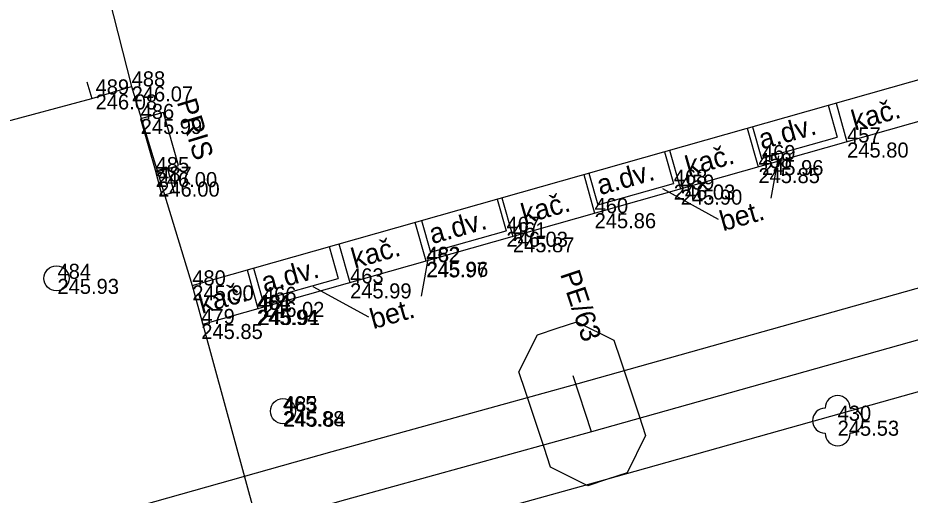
# Model space of a CAD drawing. Extents: x -599432 to -598680, y -1159407 to -1158632.
# Drawn here: x -599205.78 to -599187.97, y -1158928.37 to -1158918.84 of the extents above; entities that cross this region are included whole.
import ezdxf

# ---------------------------------------------------------------- set-up
doc = ezdxf.new("R2010")
doc.units = 0
for name, color, linetype in [('0004 VY - Body podrobné', 7, 'Continuous'), ('0005 VY - Body podrobné - čísla', 7, 'Continuous'), ('0006 VY - Body podrobné - výšky', 7, 'Continuous'), ('0007 ZA - Budova - zděná', 7, 'Continuous'), ('0007 ZAb - Budova - zděná podchodná', 7, 'Continuous'), ('0030 ZA - Chodník', 7, 'Continuous'), ('0031 ZA - Ostatní rozhraní', 7, 'Continuous'), ('0032 TE - Popis povrchu', 7, 'Continuous'), ('0035 ZA - Strom - značka', 7, 'Continuous'), ('0075 ZA - BVK - kanalizace - buňky', 7, 'Continuous'), ('0116 PV - budova převzatá z mapy', 7, 'Continuous'), ('0301 PV - RWE - popis', 7, 'Continuous'), ('0302 PV - RWE - NTL', 7, 'Continuous'), ('0303 PV - RWE - NTL přípojka', 7, 'Continuous'), ('0308 PV - RWE - ochranné pásmo', 7, 'Continuous'), ('0750 ZA - nerozlišené sítě - buňky', 7, 'Continuous'), ('0751 TE - nerozlišené sítě - popis', 7, 'Continuous')]:
    doc.layers.add(name, color=color, linetype=linetype)

msp = doc.modelspace()

# ---------------------------------------------------------------- linework, layer by layer
at = {"layer": '0004 VY - Body podrobné'}
for p, q in [((-599203.51, -1158920.21), (-599203.51, -1158920.21)), ((-599204.23, -1158920.37), (-599204.23, -1158920.37)), ((-599203.33, -1158920.86), (-599203.33, -1158920.86)), ((-599189.23, -1158921.33), (-599189.23, -1158921.33)), ((-599190.93, -1158921.68), (-599190.93, -1158921.68)), ((-599191, -1158921.84), (-599191, -1158921.84)), ((-599203.03, -1158921.92), (-599203.03, -1158921.92)), ((-599202.98, -1158922.11), (-599202.98, -1158922.11)), ((-599192.69, -1158922.17), (-599192.69, -1158922.17)), ((-599192.55, -1158922.27), (-599192.55, -1158922.27)), ((-599194.27, -1158922.74), (-599194.27, -1158922.74)), ((-599196.03, -1158923.11), (-599196.03, -1158923.11)), ((-599195.9, -1158923.22), (-599195.9, -1158923.22)), ((-599197.63, -1158923.72), (-599197.63, -1158923.72)), ((-599197.62, -1158923.71), (-599197.62, -1158923.71)), ((-599204.99, -1158924.05), (-599204.99, -1158924.05)), ((-599202.3, -1158924.18), (-599202.3, -1158924.18)), ((-599199.15, -1158924.14), (-599199.15, -1158924.14)), ((-599200.89, -1158924.51), (-599200.89, -1158924.51)), ((-599201.01, -1158924.67), (-599201.01, -1158924.67)), ((-599200.98, -1158924.67), (-599200.98, -1158924.67)), ((-599202.12, -1158924.95), (-599202.12, -1158924.95)), ((-599200.49, -1158926.69), (-599200.49, -1158926.69)), ((-599200.47, -1158926.7), (-599200.47, -1158926.7)), ((-599189.42, -1158926.88), (-599189.42, -1158926.88))]:
    msp.add_line(p, q, dxfattribs=at)
at = {"layer": '0007 ZA - Budova - zděná'}
for p, q in [((-599202.3, -1158924.18), (-599142.02, -1158907.12)), ((-599204.403, -1158920.118), (-599204.302, -1158920.451)), ((-599204.302, -1158920.451), (-599203.51, -1158920.21)), ((-599203.51, -1158920.21), (-599202.3, -1158924.18))]:
    msp.add_line(p, q, dxfattribs=at)
at = {"layer": '0007 ZAb - Budova - zděná podchodná'}
msp.add_line((-599207.036, -1158921.184), (-599204.302, -1158920.451), dxfattribs=at)
at = {"layer": '0030 ZA - Chodník'}
msp.add_line((-599202.3, -1158924.18), (-599199.63, -1158933.93), dxfattribs=at)
at = {"layer": '0031 ZA - Ostatní rozhraní'}
for p, q in [((-599202.089, -1158924.952), (-599182.511, -1158919.411)), ((-599189.607, -1158920.588), (-599189.428, -1158921.223)), ((-599189.452, -1158920.544), (-599189.235, -1158921.314)), ((-599191.225, -1158921.046), (-599191.007, -1158921.815)), ((-599191.118, -1158921.015), (-599190.938, -1158921.65)), ((-599190.938, -1158921.65), (-599189.428, -1158921.223)), ((-599192.876, -1158921.513), (-599192.696, -1158922.148)), ((-599192.773, -1158921.484), (-599192.555, -1158922.253)), ((-599194.488, -1158921.969), (-599194.27, -1158922.739)), ((-599194.387, -1158921.94), (-599194.207, -1158922.575)), ((-599194.207, -1158922.575), (-599192.696, -1158922.148)), ((-599196.215, -1158922.458), (-599196.035, -1158923.093)), ((-599196.123, -1158922.432), (-599195.905, -1158923.202)), ((-599197.856, -1158922.922), (-599197.638, -1158923.692)), ((-599197.725, -1158922.885), (-599197.546, -1158923.52)), ((-599197.546, -1158923.52), (-599196.035, -1158923.093)), ((-599199.57, -1158923.407), (-599199.391, -1158924.043)), ((-599199.373, -1158923.352), (-599199.155, -1158924.121)), ((-599201.081, -1158923.835), (-599200.901, -1158924.47)), ((-599201.206, -1158923.87), (-599200.988, -1158924.64)), ((-599200.901, -1158924.47), (-599199.391, -1158924.043))]:
    msp.add_line(p, q, dxfattribs=at)
at = {"layer": '0032 TE - Popis povrchu'}
for p, q in [((-599190.746, -1158922.443), (-599190.593, -1158921.596)), ((-599191.795, -1158922.863), (-599192.909, -1158922.257)), ((-599197.726, -1158924.396), (-599197.573, -1158923.548)), ((-599198.775, -1158924.815), (-599199.889, -1158924.21))]:
    msp.add_line(p, q, dxfattribs=at)
at = {"layer": '0035 ZA - Strom - značka'}
msp.add_circle((-599189.42, -1158926.88), 0.00025, dxfattribs=at)
for centre, start, end in [((-599189.42, -1158926.63), 0, 180), ((-599189.67, -1158926.88), 90, 270), ((-599189.17, -1158926.88), 270, 90), ((-599189.42, -1158927.13), 180, 360)]:
    msp.add_arc(centre, 0.25, start, end, dxfattribs=at)
at = {"layer": '0075 ZA - BVK - kanalizace - buňky'}
for centre in [(-599205.01, -1158924.04), (-599200.49, -1158926.69)]:
    msp.add_circle(centre, 0.25, dxfattribs=at)
at = {"layer": '0116 PV - budova převzatá z mapy'}
msp.add_line((-599205.78, -1158911.36), (-599203.51, -1158920.21), dxfattribs=at)
at = {"layer": '0302 PV - RWE - NTL'}
msp.add_lwpolyline([(-599042.76, -1158885.49), (-599068.42, -1158892.17), (-599094.54, -1158899.36), (-599103.01, -1158901.75), (-599109.28, -1158903.4), (-599121.29, -1158906.57), (-599128.03, -1158908.44), (-599139.52, -1158911.687), (-599140.38, -1158911.93), (-599166.16, -1158919.18), (-599194.33, -1158927.1), (-599199.24, -1158928.46), (-599225.65, -1158935.9)], dxfattribs=at)
at = {"layer": '0303 PV - RWE - NTL přípojka'}
msp.add_lwpolyline([(-599194.33, -1158927.1), (-599194.701, -1158925.984)], dxfattribs=at)
at = {"layer": '0308 PV - RWE - ochranné pásmo'}
msp.add_lwpolyline([(-599140.109, -1158912.892), (-599165.889, -1158920.143), (-599194.061, -1158928.063), (-599198.971, -1158929.423), (-599225.379, -1158936.863), (-599225.777, -1158936.975), (-599226.5, -1158936.57), (-599226.613, -1158936.171), (-599226.725, -1158935.773), (-599226.32, -1158935.05), (-599225.921, -1158934.937), (-599199.509, -1158927.497), (-599194.599, -1158926.137), (-599166.431, -1158918.217), (-599140.651, -1158910.968)], dxfattribs=at)
msp.add_lwpolyline([(-599195.148, -1158927.808), (-599195.279, -1158927.415), (-599195.65, -1158926.299), (-599195.78, -1158925.906), (-599195.409, -1158925.166), (-599195.016, -1158925.035), (-599194.623, -1158924.905), (-599193.883, -1158925.276), (-599193.752, -1158925.669), (-599193.381, -1158926.785), (-599193.251, -1158927.178), (-599193.622, -1158927.918), (-599194.015, -1158928.049), (-599194.408, -1158928.179)], close=True, dxfattribs=at)
at = {"layer": '0750 ZA - nerozlišené sítě - buňky'}
for points in [[(-599203.33, -1158920.86), (-599203.03, -1158921.92), (-599202.573, -1158921.791), (-599202.873, -1158920.731)], [(-599203.032, -1158921.9), (-599202.904, -1158922.384), (-599202.663, -1158922.32), (-599202.791, -1158921.836)]]:
    msp.add_lwpolyline(points, close=True, dxfattribs=at)

# ---------------------------------------------------------------- texts
at = {"layer": '0005 VY - Body podrobné - čísla'}
for s, p in [('488', (-599203.51, -1158920.21)), ('489', (-599204.23, -1158920.37)), ('486', (-599203.33, -1158920.86)), ('457', (-599189.23, -1158921.33)), ('458', (-599191, -1158921.84)), ('469', (-599190.93, -1158921.68)), ('485', (-599203.03, -1158921.92)), ('487', (-599202.98, -1158922.11)), ('468', (-599192.69, -1158922.17)), ('459', (-599192.55, -1158922.27)), ('460', (-599194.27, -1158922.74)), ('467', (-599196.03, -1158923.11)), ('461', (-599195.9, -1158923.22)), ('462', (-599197.63, -1158923.72)), ('482', (-599197.62, -1158923.71)), ('484', (-599204.99, -1158924.05)), ('463', (-599199.15, -1158924.14)), ('480', (-599202.3, -1158924.18)), ('466', (-599200.89, -1158924.51)), ('464', (-599201.01, -1158924.67)), ('481', (-599200.98, -1158924.67)), ('479', (-599202.12, -1158924.95)), ('465', (-599200.49, -1158926.69)), ('483', (-599200.47, -1158926.7)), ('430', (-599189.42, -1158926.88))]:
    msp.add_text(s, height=0.3, dxfattribs=at).set_placement(p)
at = {"layer": '0006 VY - Body podrobné - výšky'}
for s, p in [('246.07', (-599203.51, -1158920.51)), ('246.08', (-599204.23, -1158920.67)), ('245.99', (-599203.33, -1158921.16)), ('245.80', (-599189.23, -1158921.63)), ('245.96', (-599190.93, -1158921.98)), ('245.85', (-599191, -1158922.14)), ('246.00', (-599203.03, -1158922.22)), ('246.00', (-599202.98, -1158922.41)), ('246.03', (-599192.69, -1158922.47)), ('245.90', (-599192.55, -1158922.57)), ('245.86', (-599194.27, -1158923.04)), ('246.03', (-599196.03, -1158923.41)), ('245.87', (-599195.9, -1158923.52)), ('245.97', (-599197.63, -1158924.02)), ('245.96', (-599197.62, -1158924.01)), ('245.93', (-599204.99, -1158924.35)), ('245.90', (-599202.3, -1158924.48)), ('245.99', (-599199.15, -1158924.44)), ('246.02', (-599200.89, -1158924.81)), ('245.94', (-599201.01, -1158924.97)), ('245.91', (-599200.98, -1158924.97)), ('245.85', (-599202.12, -1158925.25)), ('245.88', (-599200.49, -1158926.99)), ('245.84', (-599200.47, -1158927)), ('245.53', (-599189.42, -1158927.18))]:
    msp.add_text(s, height=0.3, dxfattribs=at).set_placement(p)
at = {"layer": '0032 TE - Popis povrchu'}
for s, rotation, p in [('kač.', 15.8022, (-599189.077, -1158921.095)), ('a.dv.', 15.6438, (-599190.931, -1158921.47)), ('kač.', 15.8022, (-599192.394, -1158922.007)), ('a.dv.', 15.6438, (-599194.159, -1158922.382)), ('kač.', 15.8022, (-599195.67, -1158922.959)), ('bet.', 15.8022, (-599191.707, -1158923.102)), ('a.dv.', 15.6438, (-599197.508, -1158923.358)), ('kač.', 15.8022, (-599199.059, -1158923.847)), ('a.dv.', 15.6438, (-599200.856, -1158924.326)), ('kač.', 15.8022, (-599202.109, -1158924.75)), ('bet.', 15.8022, (-599198.687, -1158925.055))]:
    msp.add_text(s, height=0.4, rotation=rotation, dxfattribs=at).set_placement(p)
at = {"layer": '0301 PV - RWE - popis'}
msp.add_text('PE/63', height=0.4, rotation=288.3887, dxfattribs=at).set_placement((-599194.961, -1158923.953))
at = {"layer": '0751 TE - nerozlišené sítě - popis'}
msp.add_text('PRIS', height=0.4, rotation=286.9505, dxfattribs=at).set_placement((-599202.612, -1158920.519))

doc.saveas('drawing.dxf')
